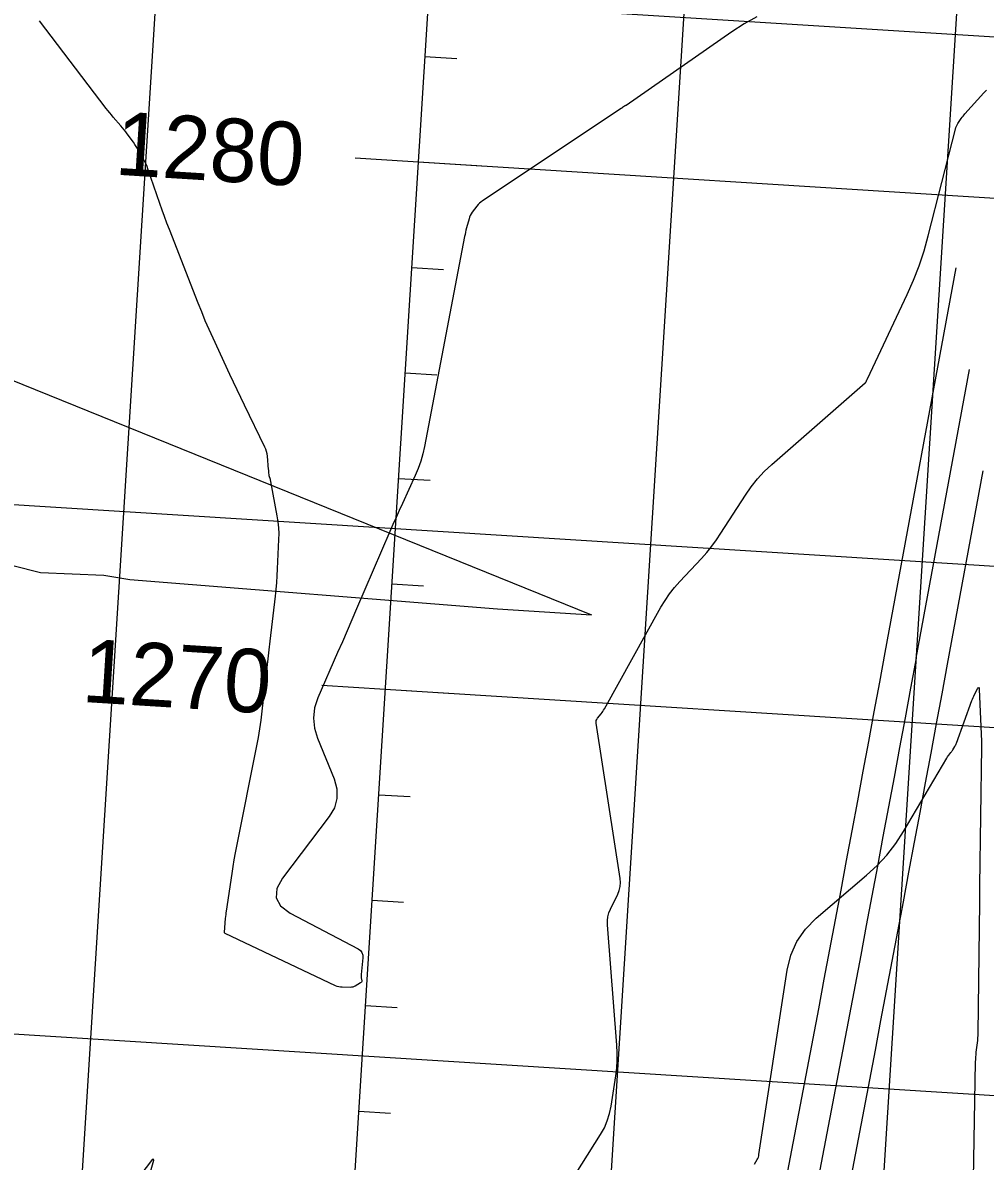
# Model space of a CAD drawing. Extents: x 658976 to 668721, y 639543 to 647196.
# Drawn here: x 661596.5 to 661687.6, y 641957.7 to 642065.5 of the extents above; entities that cross this region are included whole.
import ezdxf

# ---------------------------------------------------------------- set-up
doc = ezdxf.new("R2010")
doc.units = 0
for name, color, linetype in [('Ex_Minor Contours', 7, 'Continuous'), ('R_Axis', 7, 'Continuous'), ('R_Axis Annot', 7, 'Continuous'), ('R_Exist Surface', 7, 'Continuous'), ('R_Grid', 7, 'Continuous'), ('R_Proposed Const Limits', 7, 'Continuous'), ('R_Water', 7, 'Continuous')]:
    doc.layers.add(name, color=color, linetype=linetype)

msp = doc.modelspace()

# ---------------------------------------------------------------- linework, layer by layer
at = {"layer": 'Ex_Minor Contours'}
for points in [[(661666.02, 642066.03), (661664.81, 642065.36), (661663.64, 642064.61), (661653.62, 642057.65), (661653.61, 642057.64), (661653.6, 642057.64), (661653.59, 642057.63), (661653.58, 642057.63), (661653.54, 642057.6), (661653.54, 642057.6), (661653.53, 642057.6), (661653.53, 642057.59), (661653.52, 642057.59), (661653.5, 642057.58), (661653.49, 642057.57), (661653.48, 642057.56), (661653.29, 642057.44), (661653.25, 642057.42), (661653.22, 642057.39), (661653.18, 642057.37), (661653.15, 642057.35), (661640.02, 642048.61), (661639.87, 642048.5), (661639.74, 642048.39), (661639.61, 642048.26), (661639.5, 642048.12), (661639.06, 642047.55), (661638.96, 642047.4), (661638.88, 642047.24), (661638.81, 642047.08), (661638.76, 642046.91), (661638.53, 642046.05), (661638.47, 642045.85), (661638.43, 642045.65), (661638.38, 642045.44), (661638.34, 642045.24), (661634.55, 642025.37), (661634.39, 642024.66), (661634.19, 642023.97), (661633.95, 642023.29), (661633.67, 642022.62), (661632.45, 642019.98), (661632.15, 642019.32), (661631.86, 642018.66), (661631.56, 642017.99), (661631.27, 642017.33), (661628.12, 642009.99), (661627.67, 642008.95), (661627.22, 642007.92), (661626.77, 642006.89), (661626.32, 642005.86), (661624.45, 642001.57), (661624.14, 642000.62), (661624.03, 641999.66), (661624.12, 641998.71), (661624.41, 641997.75), (661625.98, 641993.91), (661626.25, 641992.97), (661626.26, 641992.06), (661626.01, 641991.18), (661625.51, 641990.34), (661621.1, 641984.52), (661620.55, 641983.53), (661620.49, 641982.65), (661620.92, 641981.88), (661621.83, 641981.21), (661628.25, 641977.82), (661628.47, 641977.66), (661628.62, 641977.47), (661628.7, 641977.24), (661628.71, 641976.97), (661628.55, 641975.38), (661628.55, 641975.31), (661628.55, 641975.24), (661628.55, 641975.16), (661628.56, 641975.09), (661628.6, 641974.81), (661628.61, 641974.74), (661628.59, 641974.68), (661628.55, 641974.64), (661628.5, 641974.6), (661627.98, 641974.3), (661627.87, 641974.25), (661627.76, 641974.21), (661627.64, 641974.19), (661627.52, 641974.18), (661626.76, 641974.19), (661626.6, 641974.2), (661626.44, 641974.23), (661626.28, 641974.27), (661626.13, 641974.33), (661615.67, 641979.28), (661615.64, 641979.3), (661615.62, 641979.33), (661615.61, 641979.36), (661615.6, 641979.4), (661615.72, 641980.71), (661615.74, 641980.88), (661615.76, 641981.06), (661615.78, 641981.23), (661615.81, 641981.4), (661616.33, 641984.96), (661616.43, 641985.61), (661616.54, 641986.26), (661616.66, 641986.91), (661616.78, 641987.55), (661618.66, 641997.02), (661618.82, 641997.84), (661618.95, 641998.66), (661619.07, 641999.48), (661619.18, 642000.31), (661619.55, 642003.62), (661619.65, 642004.45), (661619.74, 642005.28), (661619.84, 642006.11), (661619.94, 642006.93), (661620.44, 642011.19), (661620.51, 642011.84), (661620.57, 642012.49), (661620.61, 642013.13), (661620.64, 642013.78), (661620.76, 642016.55), (661620.77, 642017.12), (661620.75, 642017.68), (661620.69, 642018.24), (661620.6, 642018.8), (661620.01, 642022.04), (661620, 642022.09), (661619.98, 642022.14), (661619.97, 642022.18), (661619.96, 642022.23), (661619.89, 642022.42), (661619.88, 642022.47), (661619.86, 642022.51), (661619.85, 642022.56), (661619.85, 642022.61), (661619.82, 642022.93), (661619.81, 642023), (661619.81, 642023.07), (661619.8, 642023.14), (661619.79, 642023.2), (661619.67, 642024.44), (661619.64, 642024.66), (661619.59, 642024.88), (661619.52, 642025.1), (661619.43, 642025.31), (661617.51, 642029.27), (661617.16, 642029.99), (661616.82, 642030.73), (661616.47, 642031.46), (661616.13, 642032.19), (661614.53, 642035.63), (661614.15, 642036.45), (661613.79, 642037.27), (661613.45, 642038.1), (661613.11, 642038.94), (661610.39, 642045.89), (661610.15, 642046.5), (661609.92, 642047.12), (661609.7, 642047.73), (661609.48, 642048.35), (661608.36, 642051.63), (661608.28, 642051.85), (661608.19, 642052.07), (661608.08, 642052.29), (661607.97, 642052.5), (661607.5, 642053.35), (661607.38, 642053.56), (661607.25, 642053.76), (661607.12, 642053.96), (661606.98, 642054.16), (661606.4, 642054.95), (661606.26, 642055.15), (661606.11, 642055.34), (661605.95, 642055.53), (661605.8, 642055.72), (661605.08, 642056.54), (661604.91, 642056.75), (661604.74, 642056.95), (661604.58, 642057.16), (661604.41, 642057.36), (661598.09, 642065.64)], [(661645.75, 641951.57), (661651.21, 641960.26), (661651.57, 641960.89), (661651.85, 641961.55), (661652.06, 641962.23), (661652.21, 641962.93), (661652.65, 641965.81), (661652.74, 641966.53), (661652.79, 641967.26), (661652.79, 641967.98), (661652.76, 641968.71), (661651.87, 641980.1), (661651.87, 641980.49), (661651.91, 641980.86), (661652.01, 641981.23), (661652.15, 641981.59), (661652.84, 641983), (661652.98, 641983.36), (661653.07, 641983.72), (661653.09, 641984.1), (661653.06, 641984.48), (661650.8, 641999.17), (661650.79, 641999.3), (661650.81, 641999.42), (661650.86, 641999.54), (661650.93, 641999.65), (661651.27, 642000.08), (661651.35, 642000.18), (661651.43, 642000.3), (661651.5, 642000.41), (661651.57, 642000.53), (661656.93, 642010.15), (661657.32, 642010.8), (661657.74, 642011.42), (661658.2, 642012.01), (661658.7, 642012.58), (661660.76, 642014.78), (661661.26, 642015.34), (661661.74, 642015.93), (661662.18, 642016.53), (661662.6, 642017.16), (661664.92, 642020.77), (661665.46, 642021.56), (661666.06, 642022.31), (661666.71, 642023.01), (661667.42, 642023.67), (661676.27, 642031.38), (661676.29, 642031.39), (661676.3, 642031.41), (661676.31, 642031.42), (661676.32, 642031.44), (661676.36, 642031.5), (661676.37, 642031.51), (661676.38, 642031.53), (661676.39, 642031.55), (661676.39, 642031.57), (661676.43, 642031.67), (661676.44, 642031.7), (661676.45, 642031.72), (661676.46, 642031.75), (661676.47, 642031.77), (661680.24, 642039.75), (661680.84, 642041.1), (661681.37, 642042.47), (661681.84, 642043.87), (661682.24, 642045.29), (661684.81, 642055.4), (661684.85, 642055.54), (661684.9, 642055.67), (661684.97, 642055.8), (661685.04, 642055.92), (661685.36, 642056.4), (661685.44, 642056.52), (661685.53, 642056.64), (661685.62, 642056.75), (661685.71, 642056.86), (661687.48, 642058.84), (661687.76, 642059.1)], [(661665.77, 641957.45), (661666.04, 641957.88), (661666.1, 641957.99), (661666.15, 641958.11), (661666.19, 641958.23), (661666.21, 641958.35), (661668.89, 641975.8), (661669.23, 641977.23), (661669.8, 641978.52), (661670.6, 641979.68), (661671.63, 641980.72), (661676.4, 641984.78), (661677.4, 641985.7), (661678.32, 641986.7), (661679.15, 641987.78), (661679.89, 641988.92), (661683.98, 641995.87), (661684.02, 641995.94), (661684.07, 641996.01), (661684.12, 641996.08), (661684.17, 641996.14), (661684.38, 641996.39), (661684.43, 641996.46), (661684.48, 641996.52), (661684.53, 641996.59), (661684.57, 641996.66), (661684.75, 641996.98), (661684.79, 641997.06), (661684.83, 641997.14), (661684.87, 641997.22), (661684.9, 641997.3), (661686.37, 642001.32), (661686.42, 642001.46), (661686.48, 642001.6), (661686.55, 642001.74), (661686.61, 642001.88), (661686.9, 642002.43), (661686.96, 642002.53), (661687.01, 642002.55), (661687.04, 642002.51), (661687.05, 642002.39), (661687.28, 641997.45), (661687.28, 641997.4), (661687.28, 641997.36), (661687.28, 641997.32), (661687.28, 641997.27), (661687.28, 641997.1), (661687.28, 641997.06), (661687.28, 641997.01), (661687.28, 641996.97), (661687.28, 641996.93), (661687.1, 641983.82), (661687.1, 641983.69), (661687.1, 641983.56), (661687.1, 641983.43), (661687.1, 641983.29), (661687.09, 641982.76), (661687.09, 641982.63), (661687.09, 641982.5), (661687.09, 641982.36), (661687.09, 641982.23), (661686.92, 641969.84), (661686.92, 641969.62), (661686.9, 641969.39), (661686.89, 641969.16), (661686.86, 641968.94), (661686.75, 641968.03), (661686.73, 641967.81), (661686.71, 641967.58), (661686.7, 641967.36), (661686.69, 641967.13), (661686.26, 641943.13)], [(661606.92, 641955.44), (661608.84, 641957.93), (661608.85, 641957.93), (661608.86, 641957.94), (661608.87, 641957.93), (661608.87, 641957.92), (661608.89, 641957.86), (661608.89, 641957.85), (661608.89, 641957.83), (661608.89, 641957.82), (661608.89, 641957.8), (661605.43, 641945.63)]]:
    msp.add_lwpolyline(points, dxfattribs=at)
at = {"layer": 'R_Axis'}
for p, q in [((661621.43, 641852.69), (661637.1, 642102.2)), ((661634.59, 642062.28), (661637.59, 642062.09)), ((661627.98, 642052.67), (661639.95, 642051.92)), ((661633.34, 642042.31), (661636.33, 642042.13)), ((661632.71, 642032.33), (661635.71, 642032.15)), ((661632.09, 642022.35), (661635.08, 642022.17)), ((661631.46, 642012.37), (661634.45, 642012.19)), ((661624.84, 642002.77), (661636.82, 642002.02)), ((661630.21, 641992.41), (661633.2, 641992.23)), ((661629.58, 641982.43), (661632.57, 641982.24)), ((661628.95, 641972.45), (661631.95, 641972.26)), ((661628.32, 641962.47), (661631.32, 641962.28))]:
    msp.add_line(p, q, dxfattribs=at)
at = {"layer": 'R_Exist Surface'}
msp.add_lwpolyline([(661512.77, 642035.44), (661560.47, 642023.24), (661590.18, 642015.45), (661598.18, 642013.43), (661604.18, 642013.18), (661606.64, 642012.77), (661641.46, 642009.99), (661650.35, 642009.44)], dxfattribs=at)
at = {"layer": 'R_Grid'}
for p, q in [((660411.57, 642144.33), (661908.62, 642050.31)), ((661599.81, 641919.41), (661612.34, 642119.02)), ((661649.71, 641916.28), (661662.25, 642115.88)), ((661621.43, 641852.69), (661637.1, 642102.2)), ((661671.33, 641849.55), (661687, 642099.06)), ((660408.44, 642094.43), (661905.49, 642000.41)), ((661633.97, 642052.3), (663131.02, 641958.27)), ((660405.3, 642044.53), (661902.35, 641950.51)), ((661630.83, 642002.39), (663127.88, 641908.37))]:
    msp.add_line(p, q, dxfattribs=at)
at = {"layer": 'R_Proposed Const Limits'}
msp.add_lwpolyline([(661562.61, 642044.94), (661650.35, 642009.44)], dxfattribs=at)
at = {"layer": 'R_Water'}
for p, q in [((661678.15, 642005.86), (661684.87, 642042.27)), ((661681.1, 642005.32), (661686.15, 642032.66)), ((661684.05, 642004.78), (661687.43, 642023.06))]:
    msp.add_line(p, q, dxfattribs=at)
for radius in [7576.94, 7579.94, 7582.94]:
    msp.add_arc((654227.01, 643380.77), radius, 348.162318, 349.545226, dxfattribs=at)

# ---------------------------------------------------------------- texts
at = {"layer": 'R_Axis Annot'}
for s, p in [('1280', (661605.16, 642051.1)), ('1270', (661602.03, 642001.2))]:
    msp.add_text(s, height=6, rotation=356.4063, dxfattribs=at).set_placement(p)

doc.saveas('drawing.dxf')
